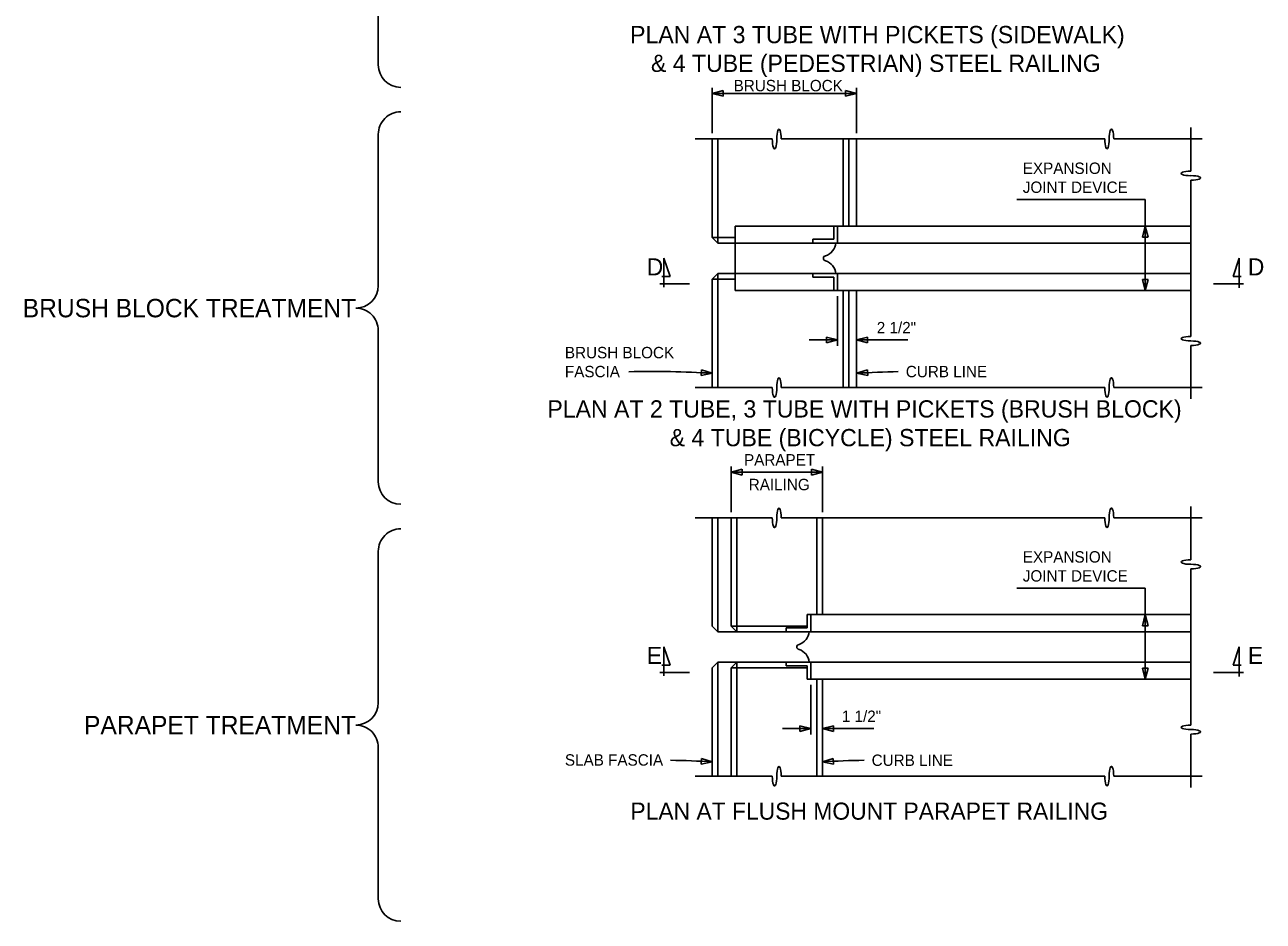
# Model space of a CAD drawing. Extents: x 19590 to 20151, y 19944 to 20103.
# Drawn here: x 19593.2 to 19643.5, y 20012 to 20048.4 of the extents above; entities that cross this region are included whole.
import ezdxf

# ---------------------------------------------------------------- set-up
doc = ezdxf.new("R2010")
doc.units = 0
for name, color, linetype in [('DETAIL_PR', 7, 'Continuous'), ('DETAIL_TEXT_DIMEN_PR', 7, 'Continuous'), ('Level 1', 7, 'Continuous')]:
    doc.layers.add(name, color=color, linetype=linetype)

msp = doc.modelspace()

# ---------------------------------------------------------------- linework, layer by layer
at = {"layer": 'DETAIL_PR'}
for p, q in [((19640.527, 20044.213), (19640.527, 20042.444)), ((19620.408, 20043.751), (19623.541, 20043.751)), ((19621.102, 20043.751), (19621.102, 20039.757)), ((19621.333, 20043.751), (19621.333, 20039.526)), ((19623.905, 20043.751), (19637.031, 20043.751)), ((19626.421, 20043.751), (19626.421, 20040.22)), ((19626.652, 20043.751), (19626.652, 20040.22)), ((19626.96, 20043.751), (19626.96, 20040.22)), ((19637.395, 20043.751), (19640.99, 20043.751)), ((19640.527, 20042.081), (19640.527, 20037.445)), ((19622.027, 20040.22), (19640.527, 20040.22)), ((19622.027, 20037.599), (19622.027, 20040.22)), ((19626.035, 20039.68), (19626.035, 20040.22)), ((19626.19, 20039.526), (19626.19, 20040.22)), ((19621.102, 20039.757), (19622.027, 20039.757)), ((19621.333, 20039.526), (19621.102, 20039.757)), ((19621.333, 20039.526), (19622.027, 20039.526)), ((19622.027, 20039.526), (19640.527, 20039.526)), ((19625.187, 20039.526), (19625.187, 20039.68)), ((19625.187, 20039.68), (19626.035, 20039.68)), ((19621.333, 20038.293), (19621.102, 20038.061)), ((19621.102, 20038.061), (19622.027, 20038.061)), ((19621.102, 20033.668), (19621.102, 20038.061)), ((19621.333, 20038.293), (19622.027, 20038.293)), ((19621.333, 20033.668), (19621.333, 20038.293)), ((19622.027, 20038.293), (19640.527, 20038.293)), ((19625.187, 20038.293), (19625.187, 20038.139)), ((19625.187, 20038.138), (19626.035, 20038.138)), ((19626.035, 20038.139), (19626.035, 20037.599)), ((19626.19, 20038.293), (19626.19, 20037.599)), ((19622.027, 20037.599), (19640.527, 20037.599)), ((19626.421, 20033.668), (19626.421, 20037.599)), ((19626.652, 20033.668), (19626.652, 20037.599)), ((19626.96, 20033.668), (19626.96, 20037.599)), ((19640.527, 20035.738), (19640.527, 20037.445)), ((19640.527, 20035.374), (19640.527, 20033.205)), ((19620.408, 20033.668), (19623.541, 20033.668)), ((19623.905, 20033.668), (19637.031, 20033.668)), ((19637.395, 20033.668), (19640.99, 20033.668)), ((19640.527, 20028.843), (19640.527, 20026.674)), ((19620.408, 20028.381), (19623.541, 20028.381)), ((19621.102, 20028.381), (19621.102, 20023.987)), ((19621.333, 20028.381), (19621.333, 20023.756)), ((19621.873, 20028.381), (19621.873, 20023.987)), ((19622.104, 20028.381), (19622.104, 20023.756)), ((19623.905, 20028.381), (19637.031, 20028.381)), ((19625.342, 20028.381), (19625.342, 20024.45)), ((19625.573, 20028.381), (19625.573, 20024.45)), ((19637.395, 20028.381), (19640.99, 20028.381)), ((19640.527, 20026.311), (19640.527, 20021.675)), ((19624.956, 20024.45), (19640.527, 20024.45)), ((19624.956, 20023.91), (19624.956, 20024.45)), ((19625.11, 20023.756), (19625.11, 20024.45)), ((19621.333, 20023.756), (19621.102, 20023.987)), ((19621.333, 20023.756), (19624.108, 20023.756)), ((19621.873, 20023.987), (19624.956, 20023.987)), ((19621.873, 20023.987), (19622.104, 20023.756)), ((19624.108, 20023.756), (19624.108, 20023.91)), ((19624.108, 20023.91), (19624.956, 20023.91)), ((19624.108, 20023.756), (19640.527, 20023.756)), ((19621.333, 20022.522), (19621.102, 20022.291)), ((19621.102, 20017.898), (19621.102, 20022.291)), ((19621.333, 20022.523), (19624.108, 20022.523)), ((19621.333, 20017.898), (19621.333, 20022.523)), ((19621.873, 20022.291), (19622.104, 20022.522)), ((19621.873, 20022.291), (19624.956, 20022.291)), ((19621.873, 20017.898), (19621.873, 20022.291)), ((19622.104, 20017.898), (19622.104, 20022.523)), ((19624.108, 20022.522), (19624.108, 20022.368)), ((19624.108, 20022.522), (19640.527, 20022.522)), ((19624.108, 20022.368), (19624.956, 20022.368)), ((19624.956, 20022.368), (19624.956, 20021.829)), ((19625.11, 20022.522), (19625.11, 20021.829)), ((19624.956, 20021.829), (19640.527, 20021.829)), ((19625.342, 20017.898), (19625.342, 20021.829)), ((19625.573, 20017.898), (19625.573, 20021.829)), ((19640.527, 20019.968), (19640.527, 20021.675)), ((19640.527, 20019.604), (19640.527, 20017.435)), ((19620.408, 20017.897), (19623.541, 20017.897)), ((19623.905, 20017.897), (19637.031, 20017.897)), ((19637.395, 20017.897), (19640.99, 20017.897))]:
    msp.add_line(p, q, dxfattribs=at)
for centre, radius, start, end in [((19625.513, 20039.591), 0.612, 288.1365, 353.9316), ((19625.711, 20038.909), 0.0999, 94.4387, 265.5613), ((19625.513, 20038.228), 0.612, 6.0684, 71.8635), ((19624.434, 20023.821), 0.612, 288.1365, 353.9316), ((19624.632, 20023.139), 0.0999, 94.4387, 265.5613), ((19624.434, 20022.458), 0.612, 6.0684, 71.8635)]:
    msp.add_arc(centre, radius, start, end, dxfattribs=at)
for centre, major_axis, ratio, start_param, end_param in [((19623.814, 20043.751), (0, -0.395), 0.230204, 1.570796, 4.712389), ((19637.304, 20043.751), (0, -0.395), 0.230204, 1.570796, 4.712389), ((19623.632, 20043.751), (0, -0.395), 0.230206, 4.712389, 7.853982), ((19637.122, 20043.751), (0, -0.395), 0.230206, 4.712389, 7.853982), ((19640.527, 20042.353), (0.395, 0), 0.230204, 1.570796, 4.712389), ((19640.527, 20042.172), (0.395, 0), 0.230206, 4.712389, 7.853982), ((19640.527, 20035.647), (0.395, 0), 0.230204, 1.570796, 4.712389), ((19640.527, 20035.465), (0.395, 0), 0.230206, 4.712389, 7.853982), ((19623.814, 20033.668), (0, -0.395), 0.230204, 1.570796, 4.712389), ((19637.304, 20033.668), (0, -0.395), 0.230204, 1.570796, 4.712389), ((19623.632, 20033.668), (0, -0.395), 0.230206, 4.712389, 7.853982), ((19637.122, 20033.668), (0, -0.395), 0.230206, 4.712389, 7.853982), ((19623.814, 20028.381), (0, -0.395), 0.230204, 1.570796, 4.712389), ((19637.304, 20028.381), (0, -0.395), 0.230204, 1.570796, 4.712389), ((19623.632, 20028.381), (0, -0.395), 0.230206, 4.712389, 7.853982), ((19637.122, 20028.381), (0, -0.395), 0.230206, 4.712389, 7.853982), ((19640.527, 20026.583), (0.395, 0), 0.230204, 1.570796, 4.712389), ((19640.527, 20026.401), (0.395, 0), 0.230206, 4.712389, 7.853982), ((19640.527, 20019.877), (0.395, 0), 0.230204, 1.570796, 4.712389), ((19640.527, 20019.695), (0.395, 0), 0.230206, 4.712389, 7.853982), ((19623.814, 20017.897), (0, -0.395), 0.230204, 1.570796, 4.712389), ((19637.304, 20017.897), (0, -0.395), 0.230204, 1.570796, 4.712389), ((19623.632, 20017.897), (0, -0.395), 0.230206, 4.712389, 7.853982), ((19637.122, 20017.897), (0, -0.395), 0.230206, 4.712389, 7.853982)]:
    msp.add_ellipse(centre, major_axis=major_axis, ratio=ratio, start_param=start_param, end_param=end_param, dxfattribs=at)
at = {"layer": 'DETAIL_TEXT_DIMEN_PR'}
for p, q in [((19607.547, 20061.377), (19607.547, 20046.757)), ((19621.102, 20043.982), (19621.102, 20045.832)), ((19621.102, 20045.601), (19626.96, 20045.601)), ((19626.96, 20043.982), (19626.96, 20045.832)), ((19607.547, 20043.941), (19607.547, 20037.756)), ((19633.465, 20041.299), (19638.677, 20041.299)), ((19638.677, 20041.299), (19638.677, 20037.599)), ((19619.137, 20037.738), (19619.136, 20038.909)), ((19619.136, 20038.909), (19619.389, 20038.173)), ((19642.493, 20038.909), (19642.239, 20038.173)), ((19642.492, 20037.711), (19642.493, 20038.909)), ((19620.177, 20037.869), (19618.971, 20037.869)), ((19619.389, 20038.173), (19619.059, 20038.173)), ((19641.452, 20037.869), (19642.668, 20037.869)), ((19642.239, 20038.173), (19642.57, 20038.173)), ((19626.19, 20035.363), (19626.19, 20037.368)), ((19607.547, 20035.98), (19607.547, 20029.837)), ((19625.033, 20035.595), (19626.19, 20035.595)), ((19626.96, 20035.595), (19629.042, 20035.595)), ((19621.873, 20028.612), (19621.873, 20030.462)), ((19625.573, 20028.612), (19625.573, 20030.462)), ((19621.873, 20030.231), (19625.573, 20030.231)), ((19607.547, 20027.022), (19607.547, 20020.837)), ((19633.465, 20025.529), (19638.677, 20025.529)), ((19638.677, 20025.529), (19638.677, 20021.829)), ((19619.137, 20021.968), (19619.136, 20023.139)), ((19619.136, 20023.139), (19619.389, 20022.403)), ((19642.493, 20023.139), (19642.239, 20022.403)), ((19642.492, 20021.941), (19642.493, 20023.139)), ((19619.389, 20022.403), (19619.059, 20022.403)), ((19642.239, 20022.403), (19642.57, 20022.403)), ((19620.177, 20022.099), (19618.971, 20022.099)), ((19641.452, 20022.099), (19642.668, 20022.099)), ((19625.11, 20019.593), (19625.11, 20021.598)), ((19623.954, 20019.825), (19625.11, 20019.825)), ((19625.573, 20019.825), (19627.654, 20019.825)), ((19607.547, 20019.061), (19607.547, 20012.918))]:
    msp.add_line(p, q, dxfattribs=at)
for centre, radius, start, end in [((19608.457, 20046.757), 0.91, 180.0337, 270.0337), ((19608.457, 20043.941), 0.91, 89.9663, 180.0337), ((19606.637, 20037.8), 0.911, 269.9663, 359.9663), ((19606.637, 20035.979), 0.91, 359.9663, 90.0337), ((19618.675, 19995.168), 39.151, 86.4465, 91.4029), ((19629.387, 19995.168), 39.151, 91.0778, 93.5535), ((19608.457, 20029.838), 0.91, 180.0337, 270.0337), ((19608.457, 20027.022), 0.91, 89.9663, 180.0337), ((19606.637, 20020.881), 0.911, 269.9663, 359.9663), ((19606.637, 20019.06), 0.91, 359.9663, 90.0337), ((19618.675, 19979.398), 39.151, 86.4465, 88.9222), ((19628, 19979.398), 39.151, 91.0778, 93.5535), ((19608.457, 20012.919), 0.91, 180.0337, 270.0337)]:
    msp.add_arc(centre, radius, start, end, dxfattribs=at)
at = {"layer": 'Level 1'}
for p, q in [((19621.55, 20045.717), (19621.102, 20045.601)), ((19621.102, 20045.601), (19621.55, 20045.485)), ((19621.55, 20045.485), (19621.55, 20045.717)), ((19626.512, 20045.485), (19626.512, 20045.717)), ((19626.512, 20045.717), (19626.96, 20045.601)), ((19626.96, 20045.601), (19626.512, 20045.485)), ((19638.561, 20039.773), (19638.677, 20040.22)), ((19638.677, 20040.22), (19638.793, 20039.773)), ((19638.793, 20039.773), (19638.561, 20039.773)), ((19638.793, 20038.047), (19638.561, 20038.047)), ((19638.561, 20038.047), (19638.677, 20037.599)), ((19638.677, 20037.599), (19638.793, 20038.047)), ((19625.741, 20035.479), (19625.741, 20035.71)), ((19625.741, 20035.71), (19626.19, 20035.595)), ((19626.19, 20035.595), (19625.741, 20035.479)), ((19627.408, 20035.71), (19626.96, 20035.595)), ((19626.96, 20035.595), (19627.408, 20035.479)), ((19627.408, 20035.479), (19627.408, 20035.71)), ((19620.648, 20034.153), (19620.661, 20034.385)), ((19620.661, 20034.385), (19621.102, 20034.244)), ((19626.96, 20034.244), (19627.401, 20034.385)), ((19627.401, 20034.385), (19627.414, 20034.153)), ((19621.102, 20034.244), (19620.648, 20034.153)), ((19627.414, 20034.153), (19626.96, 20034.244)), ((19622.321, 20030.347), (19621.873, 20030.231)), ((19622.321, 20030.115), (19622.321, 20030.347)), ((19625.125, 20030.347), (19625.573, 20030.231)), ((19625.125, 20030.115), (19625.125, 20030.347)), ((19621.873, 20030.231), (19622.321, 20030.115)), ((19625.573, 20030.231), (19625.125, 20030.115)), ((19638.561, 20024.002), (19638.677, 20024.45)), ((19638.677, 20024.45), (19638.793, 20024.002)), ((19638.793, 20024.002), (19638.561, 20024.002)), ((19638.793, 20022.277), (19638.561, 20022.277)), ((19638.561, 20022.277), (19638.677, 20021.829)), ((19638.677, 20021.829), (19638.793, 20022.277)), ((19624.662, 20019.709), (19624.662, 20019.94)), ((19624.662, 20019.94), (19625.11, 20019.825)), ((19625.11, 20019.825), (19624.662, 20019.709)), ((19626.021, 20019.94), (19625.573, 20019.825)), ((19625.573, 20019.825), (19626.021, 20019.709)), ((19626.021, 20019.709), (19626.021, 20019.94)), ((19620.648, 20018.383), (19620.661, 20018.614)), ((19621.102, 20018.473), (19620.648, 20018.383)), ((19620.661, 20018.614), (19621.102, 20018.473)), ((19625.573, 20018.473), (19626.014, 20018.614)), ((19626.027, 20018.383), (19625.573, 20018.473)), ((19626.014, 20018.614), (19626.027, 20018.383))]:
    msp.add_line(p, q, dxfattribs=at)

# ---------------------------------------------------------------- texts
at = {"layer": 'DETAIL_TEXT_DIMEN_PR'}
for s, height, p in [('PLAN AT 3 TUBE WITH PICKETS (SIDEWALK)', 0.69987, (19617.769, 20047.639)), (' & 4 TUBE (PEDESTRIAN) STEEL RAILING', 0.69987, (19618.355, 20046.473)), ('BRUSH BLOCK', 0.4625, (19621.97, 20045.686)), ('EXPANSION ', 0.4625, (19633.707, 20042.333)), ('JOINT DEVICE', 0.4625, (19633.707, 20041.562)), ('D', 0.694, (19618.443, 20038.216)), ('D', 0.694, (19642.84, 20038.216)), ('2 1/2"', 0.4625, (19627.78, 20035.865)), ('BRUSH BLOCK', 0.4625, (19615.122, 20034.852)), ('FASCIA', 0.4625, (19615.122, 20034.082)), ('CURB LINE', 0.4625, (19628.959, 20034.082)), ('PLAN AT 2 TUBE, 3 TUBE WITH PICKETS (BRUSH BLOCK)', 0.69987, (19614.412, 20032.449)), (' & 4 TUBE (BICYCLE) STEEL RAILING', 0.69987, (19619.115, 20031.283)), ('PARAPET', 0.4625, (19622.392, 20030.501)), ('RAILING', 0.4625, (19622.584, 20029.499)), ('EXPANSION ', 0.4625, (19633.707, 20026.562)), ('JOINT DEVICE', 0.4625, (19633.707, 20025.791)), ('E', 0.694, (19618.443, 20022.446)), ('E', 0.694, (19642.84, 20022.446)), ('1 1/2"', 0.4625, (19626.362, 20020.095)), ('SLAB FASCIA', 0.4625, (19615.122, 20018.322)), ('CURB LINE', 0.4625, (19627.572, 20018.311)), ('PLAN AT FLUSH MOUNT PARAPET RAILING', 0.69385, (19617.78, 20016.13))]:
    msp.add_text(s, height=height, dxfattribs=at).set_placement(p)
for s, p in [('BRUSH BLOCK TREATMENT', (19593.118, 20036.516)), ('PARAPET TREATMENT', (19595.606, 20019.597))]:
    msp.add_text(s, height=0.74643, rotation=360, dxfattribs=at).set_placement(p)

doc.saveas('drawing.dxf')
